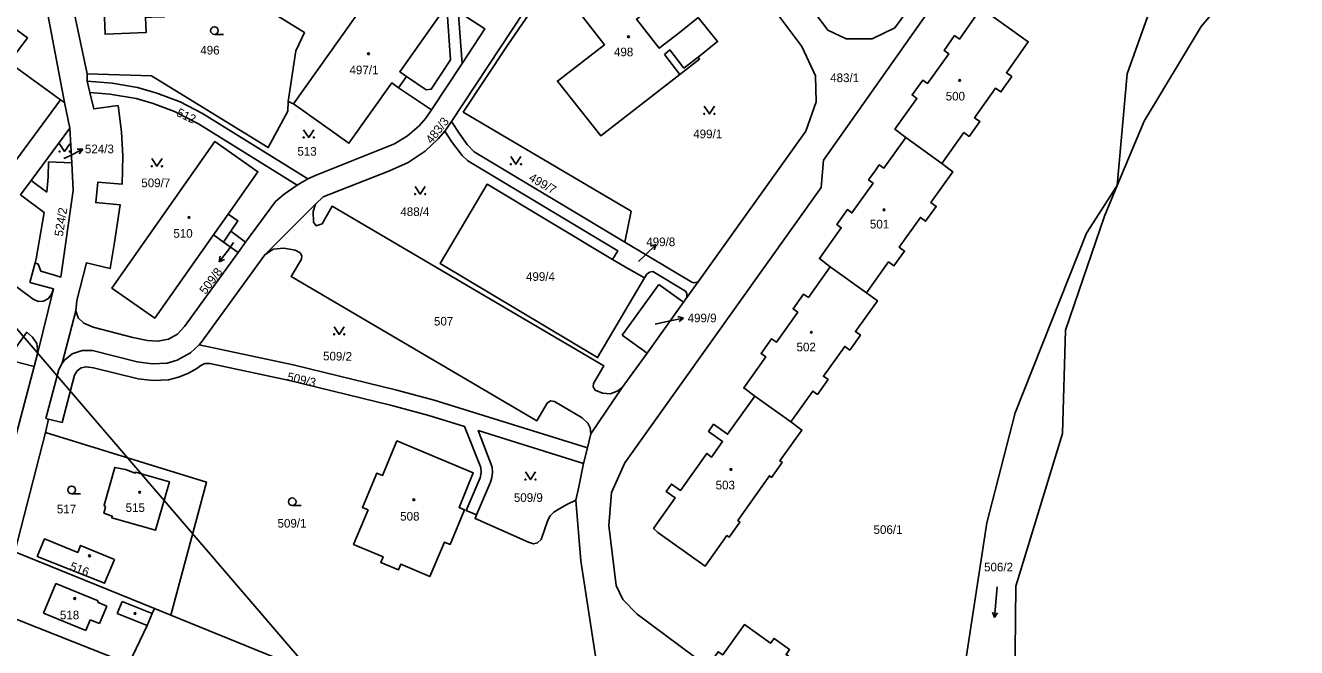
# Model space of a CAD drawing. Extents: x -558358 to -557517, y -1073785 to -1073189.
# Drawn here: x -558075.9 to -557826.1, y -1073555.9 to -1073433.6 of the extents above; entities that cross this region are included whole.
import ezdxf

# ---------------------------------------------------------------- set-up
doc = ezdxf.new("R2010")
doc.units = 0
for name, color, linetype in [('Hranice parcel', 7, 'Continuous'), ('Parcelní čísla', 7, 'Continuous'), ('Pop  PČ popisy', 7, 'Continuous'), ('Vnitřní kresba', 7, 'Continuous'), ('Vrstva 28', 7, 'Continuous'), ('Značky budov', 7, 'Continuous'), ('Značky kultur', 7, 'Continuous')]:
    doc.layers.add(name, color=color, linetype=linetype)

msp = doc.modelspace()

# ---------------------------------------------------------------- linework, layer by layer
at = {"layer": 'Hranice parcel'}
for p, q in [((-558068.26, -1073448.76), (-558079.07, -1073390.9)), ((-558069.9, -1073413.89), (-558063.79, -1073443.12)), ((-558079.09, -1073440.91), (-558069.01, -1073448.19)), ((-557996.12, -1073450.19), (-557990.11, -1073441.11)), ((-558063.79, -1073443.12), (-558063.8, -1073444.57)), ((-558001.05, -1073443.62), (-558002.62, -1073445.83)), ((-558001.05, -1073443.62), (-557997.16, -1073446.28)), ((-558063.8, -1073444.57), (-558063.26, -1073446.76)), ((-557996.12, -1073450.19), (-558002.62, -1073445.83)), ((-558069.01, -1073448.19), (-558068.26, -1073448.76)), ((-558067.19, -1073453.76), (-558068.26, -1073448.76)), ((-558023.22, -1073448.98), (-558024.27, -1073448.53)), ((-558074.8, -1073464.07), (-558067.19, -1073453.76)), ((-558067.19, -1073453.76), (-558066.82, -1073460.61)), ((-557993.5, -1073454.4), (-557992.19, -1073452.45)), ((-557902.93, -1073455.63), (-557895.8, -1073460.74)), ((-557987.76, -1073458.45), (-557958.11, -1073476.19)), ((-558071.37, -1073460.39), (-558066.82, -1073460.61)), ((-558022.54, -1073464.96), (-558020.42, -1073463.73)), ((-558076.9, -1073466.92), (-558074.8, -1073464.07)), ((-558074.8, -1073464.07), (-558071.72, -1073466.37)), ((-558076.9, -1073466.92), (-558072.2, -1073470.34)), ((-558018.89, -1073468.72), (-558028.88, -1073478.68)), ((-558072.2, -1073470.34), (-558073.77, -1073479.5)), ((-558037.01, -1073476.18), (-558035.54, -1073474.05)), ((-558037.01, -1073476.18), (-558034.12, -1073478.2)), ((-558032.65, -1073476.17), (-558035.54, -1073474.05)), ((-558032.65, -1073476.17), (-558034.12, -1073478.2)), ((-557958.11, -1073476.19), (-557944.96, -1073484.06)), ((-558073.98, -1073480.28), (-558075.03, -1073484.15)), ((-558073.77, -1073479.5), (-558073.98, -1073480.28)), ((-557917.76, -1073481.02), (-557910.62, -1073486.13)), ((-558075.03, -1073484.15), (-558070.38, -1073485.35)), ((-558070.38, -1073485.35), (-558073.57, -1073498.15)), ((-557958.62, -1073494.5), (-557951.44, -1073484.51)), ((-557951.44, -1073484.51), (-557946.6, -1073487.99)), ((-557943.74, -1073483.99), (-557945.94, -1073487.07)), ((-557944.96, -1073484.06), (-557944.51, -1073484.17)), ((-557944.51, -1073484.17), (-557943.74, -1073483.99)), ((-557946.6, -1073487.99), (-557953.75, -1073497.99)), ((-557945.94, -1073487.07), (-557946.6, -1073487.99)), ((-557945.94, -1073487.07), (-557945.95, -1073486.25)), ((-558068.7, -1073499.98), (-558066, -1073489.71)), ((-557953.75, -1073497.99), (-557958.62, -1073494.5)), ((-558074.22, -1073500.6), (-558073.57, -1073498.15)), ((-557953.75, -1073497.99), (-557958.67, -1073504.77)), ((-558074.22, -1073500.6), (-558078.34, -1073516.28)), ((-558078.27, -1073499.57), (-558074.22, -1073500.6)), ((-557964.79, -1073513.87), (-557958.67, -1073504.77)), ((-557932.61, -1073506.45), (-557925.51, -1073511.53)), ((-558071.35, -1073510.96), (-558072, -1073513.63)), ((-558071.35, -1073510.96), (-558071.87, -1073510.83)), ((-558068.72, -1073511.63), (-558071.35, -1073510.96)), ((-558072, -1073513.63), (-558078.01, -1073537.04)), ((-557965.43, -1073516.64), (-557964.79, -1073513.87)), ((-557872.13, -1073513.82), (-557881.3, -1073543.83)), ((-557965.43, -1073516.64), (-557966.22, -1073519.7)), ((-557966.22, -1073519.7), (-557967.17, -1073524.31)), ((-557967.17, -1073524.31), (-557967.76, -1073526.9)), ((-557967.76, -1073526.9), (-557969.49, -1073527.78)), ((-558078.01, -1073537.04), (-558050.57, -1073548.21)), ((-558050.57, -1073548.21), (-558047.33, -1073549.53)), ((-558080.96, -1073549.01), (-558055.56, -1073559.09))]:
    msp.add_line(p, q, dxfattribs=at)
for points in [[(-558022.09, -1073311.21), (-558020.08, -1073313.87), (-558000.41, -1073328.2), (-557993.92, -1073334.5), (-557986.04, -1073343.93), (-557967.1, -1073369.2), (-557918.24, -1073434.51), (-557914.64, -1073436.24), (-557909.55, -1073436.22), (-557905.05, -1073434.1), (-557902.57, -1073430.65), (-557891.22, -1073414.37), (-557877.97, -1073395.43)], [(-557997.16, -1073446.28), (-557996.18, -1073446.14), (-557992.37, -1073440.37), (-557993.13, -1073429.99), (-557993.58, -1073428.02), (-558004.25, -1073395), (-558005.55, -1073391.58), (-558006.57, -1073389.94), (-558009.69, -1073386.81), (-558015.69, -1073381.13), (-558022.86, -1073375.1), (-558038.38, -1073364.54), (-558051.46, -1073355.75)], [(-557861.36, -1073465.07), (-557859.38, -1073443.12), (-557853.44, -1073426.35), (-557845.8, -1073410.81), (-557826.12, -1073387.26)], [(-557990.11, -1073441.11), (-557990.95, -1073429.72), (-557991.6, -1073426.99), (-558000.34, -1073399.97), (-557986.42, -1073409.86), (-557979.13, -1073399.38), (-557977.23, -1073400.7), (-557975.75, -1073398.59), (-557966.19, -1073404.96)], [(-557943.74, -1073483.99), (-557922.57, -1073454.37), (-557920.54, -1073448.62), (-557920.67, -1073443.5), (-557923.32, -1073437.76), (-557933.57, -1073424.07), (-557935, -1073422.19), (-557950.81, -1073400.97)], [(-557966.19, -1073404.96), (-557967.15, -1073406.3), (-557970.9, -1073403.86), (-557989.34, -1073431.82), (-557985.62, -1073434.28), (-557990.11, -1073441.11)], [(-557960.73, -1073418.81), (-557955.07, -1073414.41), (-557951.22, -1073411.42), (-557950.93, -1073411.8), (-557947.21, -1073416.59), (-557951.08, -1073419.63), (-557946.63, -1073425.3), (-557955.8, -1073432.39), (-557951.37, -1073438.08), (-557947.44, -1073435.04), (-557943.73, -1073432.04), (-557939.89, -1073436.78), (-557943.7, -1073439.86), (-557943.42, -1073440.21), (-557947.29, -1073443.23), (-557962.81, -1073455.3), (-557971.36, -1073444.52), (-557962.13, -1073437.38), (-557970.6, -1073426.47), (-557970.03, -1073426.04)], [(-557875.08, -1073418.52), (-557880.11, -1073415), (-557884.66, -1073414.11), (-557888.78, -1073417.07), (-557919.08, -1073460.09), (-557919.51, -1073465.45), (-557958.15, -1073519.56), (-557960.76, -1073525.37), (-557961.25, -1073531.9), (-557959.85, -1073543.64), (-557958.52, -1073546.41), (-557955.67, -1073549.33), (-557941.9, -1073559.58)], [(-558079.09, -1073440.91), (-558075.49, -1073436.06), (-558080.13, -1073432.64), (-558078.53, -1073430.7), (-558082.12, -1073428.01), (-558083.47, -1073429.99), (-558090.26, -1073424.91), (-558087.3, -1073420.92), (-558091.08, -1073418.03), (-558093.98, -1073421.97), (-558100.23, -1073417.28)], [(-557968.81, -1073419.39), (-557969.8, -1073419.14), (-557970.66, -1073419.77), (-557992.19, -1073452.45)], [(-557834.15, -1073421.11), (-557844.86, -1073433.81), (-557856.07, -1073452.41), (-557861.36, -1073465.07)], [(-558049.8, -1073431.93), (-558048.54, -1073431.88), (-558048.64, -1073429.15), (-558049.91, -1073429.2), (-558050.08, -1073422.86), (-558052.56, -1073422.66), (-558052.57, -1073422.02), (-558060.76, -1073422.24), (-558060.26, -1073435.32), (-558052.21, -1073435.02), (-558052.32, -1073432.02), (-558049.8, -1073431.93)], [(-558023.22, -1073448.98), (-558004.82, -1073423.06), (-557993.94, -1073430.83), (-558002.36, -1073442.69), (-558001.05, -1073443.62)], [(-557971.99, -1073423.64), (-557977.49, -1073432.15), (-557981.25, -1073437.64), (-557989.89, -1073450.63)], [(-558024.27, -1073448.53), (-558022.77, -1073438.58), (-558021.1, -1073435.02), (-558027.22, -1073431.17)], [(-557902.93, -1073455.63), (-557905.05, -1073454), (-557900.72, -1073447.94), (-557901.66, -1073447.27), (-557899.55, -1073444.33), (-557898.62, -1073444.99), (-557894.46, -1073439.18), (-557895.4, -1073438.51), (-557893.33, -1073435.61), (-557892.39, -1073436.28), (-557888.07, -1073430.23), (-557878.84, -1073436.82), (-557883.15, -1073442.9), (-557882.08, -1073443.65), (-557884.22, -1073446.66), (-557885.28, -1073445.91), (-557889.41, -1073451.73), (-557888.35, -1073452.48), (-557890.43, -1073455.41), (-557891.49, -1073454.66), (-557895.8, -1073460.74)], [(-558063.79, -1073443.12), (-558051.12, -1073443.51), (-558028.21, -1073457.62), (-558024.35, -1073450.45), (-558024.27, -1073448.53)], [(-558020.42, -1073463.73), (-558041.1, -1073450.88), (-558045.53, -1073448.61), (-558050.06, -1073446.9), (-558053.87, -1073445.77), (-558058.84, -1073444.97), (-558063.8, -1073444.57)], [(-558002.62, -1073445.83), (-558003.93, -1073444.91), (-558012.33, -1073456.75), (-558023.22, -1073448.98)], [(-558069.01, -1073448.19), (-558089.39, -1073475.8), (-558089.17, -1073475.95), (-558090.09, -1073477.27), (-558100.29, -1073469.58), (-558095.61, -1073463.24)], [(-558066, -1073489.71), (-558065.83, -1073487.66), (-558063.93, -1073480.27), (-558059.28, -1073481.39), (-558058.41, -1073476.28), (-558057.32, -1073468.85), (-558062.09, -1073468.41), (-558061.69, -1073464.41), (-558056.9, -1073464.79), (-558056.8, -1073459.32), (-558057.06, -1073454.51), (-558057.72, -1073449.34), (-558062.47, -1073450), (-558063.26, -1073446.76)], [(-558063.26, -1073446.76), (-558059.34, -1073447.1), (-558054.18, -1073447.94), (-558050.82, -1073448.92), (-558046.65, -1073450.5), (-558041.92, -1073452.93), (-558022.54, -1073464.96)], [(-558020.42, -1073463.73), (-558018.76, -1073463.03), (-558003.4, -1073456.89), (-558000.84, -1073455.32), (-557998.53, -1073453.34), (-557997.26, -1073451.83), (-557996.12, -1073450.19)], [(-557989.89, -1073450.63), (-557956.91, -1073470.13), (-557958.11, -1073476.19)], [(-557992.19, -1073452.45), (-557990.57, -1073454.98), (-557989.11, -1073456.98), (-557987.76, -1073458.45)], [(-558018.89, -1073468.72), (-558017.43, -1073467.28), (-558004.36, -1073462.2), (-558000.71, -1073460.54), (-557997.38, -1073458.33), (-557994.81, -1073455.9), (-557993.5, -1073454.4)], [(-557960.53, -1073479.61), (-557959.52, -1073477.88), (-557988.99, -1073460.22), (-557990.09, -1073459.14), (-557992.19, -1073456.42), (-557993.5, -1073454.4)], [(-557917.76, -1073481.02), (-557919.89, -1073479.42), (-557915.58, -1073473.37), (-557916.49, -1073472.72), (-557914.4, -1073469.79), (-557913.49, -1073470.44), (-557909.33, -1073464.6), (-557910.24, -1073463.95), (-557908.96, -1073462.17), (-557908.15, -1073461.02), (-557907.24, -1073461.67), (-557902.93, -1073455.63)], [(-558035.54, -1073474.05), (-558034.14, -1073472.03), (-558036.08, -1073470.66), (-558030.24, -1073462.37), (-558038.66, -1073456.4), (-558058.9, -1073485.25), (-558050.49, -1073491.12), (-558038.98, -1073474.78), (-558037.01, -1073476.18)], [(-558066.82, -1073460.61), (-558066.53, -1073466.05), (-558068.98, -1073483.05), (-558070.17, -1073482.68), (-558072.89, -1073481.86), (-558073.42, -1073480.5), (-558073.98, -1073480.28)], [(-558071.72, -1073466.37), (-558071.45, -1073463.36), (-558071.37, -1073460.39)], [(-557895.8, -1073460.74), (-557893.65, -1073462.39), (-557897.97, -1073468.43), (-557896.94, -1073469.17), (-557899.02, -1073472.08), (-557900.05, -1073471.34), (-557904.22, -1073477.17), (-557903.16, -1073477.93), (-557905.25, -1073480.84), (-557906.3, -1073480.09), (-557910.62, -1073486.13)], [(-558022.54, -1073464.96), (-558025.08, -1073466.74), (-558026.8, -1073468.19), (-558032.65, -1073476.17)], [(-557954.23, -1073483.22), (-557963.48, -1073498.87), (-557994.38, -1073480.4), (-557985.2, -1073464.81), (-557960.53, -1073479.61)], [(-557897.48, -1073592.57), (-557892.38, -1073566.43), (-557887.02, -1073531.37), (-557881.44, -1073509.74), (-557867.37, -1073474.4), (-557861.36, -1073465.07)], [(-557861.36, -1073465.07), (-557863.88, -1073471.1), (-557871.54, -1073493.51), (-557872.13, -1073513.82)], [(-557958.67, -1073504.77), (-557959.52, -1073505.42), (-557960.94, -1073505.97), (-557962.48, -1073505.9), (-557963.93, -1073505.3), (-557964.34, -1073504.64), (-557964.29, -1073503.98), (-557962.25, -1073500.52), (-558015.64, -1073469.14), (-558017.62, -1073472.56), (-558018.8, -1073472.98), (-558019.32, -1073472.29), (-558019.38, -1073470.18), (-558018.89, -1073468.72)], [(-558073.57, -1073498.15), (-558073.51, -1073497.13), (-558073.7, -1073496.11), (-558074.52, -1073494.85), (-558075.64, -1073493.89), (-558078.28, -1073497.56), (-558092.71, -1073486.96), (-558086.45, -1073478.46)], [(-558070.38, -1073485.35), (-558070.76, -1073486.43), (-558071.41, -1073487.24), (-558072.33, -1073487.8), (-558073.38, -1073487.88), (-558074.36, -1073487.41), (-558086.45, -1073478.46)], [(-558034.12, -1073478.2), (-558044.67, -1073492.79), (-558046.03, -1073494.25), (-558047.82, -1073495.28), (-558049.88, -1073495.66), (-558051.92, -1073495.51), (-558054.81, -1073494.91), (-558062.59, -1073492.91), (-558064.44, -1073492.11), (-558065.56, -1073491.04), (-558066, -1073489.71)], [(-558028.88, -1073478.68), (-558041.38, -1073495.88), (-558041.79, -1073496.35)], [(-558028.88, -1073478.68), (-558027.22, -1073477.58), (-558025.14, -1073477.37), (-558022.91, -1073477.77), (-558021.94, -1073478.27), (-558021.58, -1073478.9), (-558021.69, -1073479.54), (-558023.7, -1073482.95), (-557975.42, -1073511.29), (-557973.41, -1073507.84), (-557972.71, -1073507.36), (-557971.95, -1073507.53), (-557966.49, -1073510.72), (-557965.39, -1073511.77), (-557964.96, -1073512.7), (-557964.79, -1073513.87)], [(-557954.23, -1073483.22), (-557957.38, -1073481.46), (-557960.53, -1073479.61)], [(-557932.61, -1073506.45), (-557934.75, -1073504.84), (-557930.41, -1073498.76), (-557931.35, -1073498.09), (-557930.07, -1073496.31), (-557929.28, -1073495.19), (-557928.34, -1073495.86), (-557924.14, -1073489.96), (-557925.07, -1073489.3), (-557922.99, -1073486.39), (-557922.06, -1073487.05), (-557917.76, -1073481.02)], [(-557945.95, -1073486.25), (-557946.2, -1073485.81), (-557952.65, -1073481.96), (-557953.3, -1073482.07), (-557953.78, -1073482.47), (-557954.23, -1073483.22)], [(-557910.62, -1073486.13), (-557908.48, -1073487.72), (-557912.81, -1073493.77), (-557911.82, -1073494.47), (-557913.92, -1073497.39), (-557914.9, -1073496.69), (-557919.09, -1073502.55), (-557918.19, -1073503.19), (-557920.29, -1073506.11), (-557921.18, -1073505.47), (-557925.51, -1073511.53)], [(-558068.7, -1073499.98), (-558068.26, -1073499.37), (-558066.7, -1073498.15), (-558064.79, -1073497.48), (-558062.72, -1073497.49), (-558053.98, -1073499.73), (-558051.03, -1073500.12), (-558048.06, -1073499.96), (-558046.1, -1073499.41), (-558043.49, -1073497.93), (-558041.79, -1073496.35)], [(-558041.79, -1073496.35), (-558023.3, -1073500.28), (-558002.91, -1073505.27), (-557995.6, -1073507.26), (-557965.43, -1073516.64)], [(-558071.87, -1073510.83), (-558069.32, -1073501.19), (-558068.7, -1073499.98)], [(-557987.27, -1073529.77), (-557989.29, -1073528.94), (-557986.56, -1073522.48), (-557986.36, -1073521.52), (-557986.44, -1073520.51), (-557989.6, -1073512.4), (-557996.64, -1073510.25), (-558004.14, -1073508.22), (-558024.01, -1073503.35), (-558039.66, -1073500.03), (-558040.64, -1073500.03), (-558041.42, -1073500.4), (-558042.23, -1073501), (-558043.97, -1073502.01), (-558045.84, -1073502.74), (-558047.8, -1073503.22), (-558050.8, -1073503.37), (-558053.79, -1073503.03), (-558062.52, -1073500.9), (-558063.99, -1073500.68), (-558064.96, -1073500.91), (-558065.77, -1073501.48), (-558066.28, -1073502.33), (-558068.72, -1073511.63)], [(-557932.61, -1073506.45), (-557937.92, -1073513.94), (-557940.69, -1073511.97), (-557941.71, -1073513.4), (-557938.93, -1073515.37), (-557941.12, -1073518.46), (-557942.01, -1073517.7), (-557947.21, -1073524.97), (-557948.97, -1073523.73), (-557949.99, -1073525.17), (-557948.24, -1073526.41), (-557952.49, -1073532.47), (-557951.63, -1073533.27), (-557942.33, -1073539.86), (-557938.05, -1073533.83), (-557937.62, -1073534.14), (-557935.52, -1073531.19), (-557935.95, -1073530.88), (-557929.72, -1073522.11), (-557929.27, -1073522.43), (-557927.19, -1073519.5), (-557927.64, -1073519.19), (-557923.33, -1073513.13), (-557925.51, -1073511.53)], [(-558047.33, -1073549.53), (-558040.31, -1073523.33), (-558072, -1073513.63)], [(-557987.27, -1073529.77), (-557984.55, -1073523.36), (-557984.23, -1073522.42), (-557984.14, -1073521.45), (-557984.2, -1073520.39), (-557986.94, -1073513.23), (-557966.22, -1073519.7)], [(-558008.57, -1073528.8), (-558011.42, -1073535.59), (-558005.63, -1073538.02), (-558006.1, -1073539.13), (-558002.62, -1073540.59), (-558002.16, -1073539.49), (-557996.41, -1073541.91), (-557993.56, -1073535.14), (-557992.45, -1073535.6), (-557989.61, -1073528.81), (-557990.71, -1073528.34), (-557987.91, -1073521.54), (-558002.9, -1073515.24), (-558005.74, -1073522.02), (-558006.84, -1073521.56), (-558009.68, -1073528.33), (-558008.57, -1073528.8)], [(-558060.16, -1073528.26), (-558060.48, -1073529.48), (-558058.86, -1073530.06), (-558058.94, -1073530.35), (-558050.37, -1073532.81), (-558047.63, -1073523.32), (-558054.29, -1073521.4), (-558054.34, -1073521.59), (-558056.23, -1073520.85), (-558058.32, -1073520.45), (-558060.47, -1073527.85), (-558060.16, -1073528.26)], [(-557969.49, -1073527.78), (-557971.24, -1073528.71), (-557972.09, -1073529.24), (-557972.78, -1073529.97), (-557973.26, -1073530.86), (-557974.57, -1073534.63), (-557975.26, -1073535.31), (-557976.1, -1073535.45), (-557977.05, -1073535.17), (-557987.55, -1073530.47), (-557987.27, -1073529.77)], [(-557961.12, -1073576.24), (-557962.13, -1073568.62), (-557962.94, -1073563.5), (-557966.76, -1073538.79), (-557967.76, -1073526.9)], [(-558058.43, -1073538.53), (-558065.06, -1073535.79), (-558065.61, -1073537.16), (-558072.15, -1073534.51), (-558073.59, -1073537.94), (-558060.37, -1073543.23), (-558058.43, -1073538.53)], [(-557881.3, -1073543.83), (-557881.54, -1073569.39), (-557886.18, -1073582.51)], [(-558055.56, -1073559.09), (-558052.02, -1073551.52), (-558051, -1073549.15), (-558050.57, -1073548.21)], [(-557977.41, -1073591.02), (-557981.5, -1073577.12), (-557984.25, -1073575.17), (-558047.33, -1073549.53)], [(-557944.07, -1073562.64), (-557943.15, -1073563.3), (-557947.42, -1073569.28), (-557934.16, -1073578.7), (-557929.93, -1073572.77), (-557928.96, -1073573.46), (-557924.72, -1073567.52), (-557925.63, -1073566.74), (-557921.33, -1073560.9), (-557926.44, -1073557.23), (-557925.76, -1073556.27), (-557928.81, -1073554.08), (-557929.5, -1073555.03), (-557934.61, -1073551.36), (-557938.85, -1073557.29), (-557939.81, -1073556.68), (-557941.9, -1073559.58)]]:
    msp.add_lwpolyline(points, dxfattribs=at)
at = {"layer": 'Pop  PČ popisy'}
for p, q in [((-558067.34, -1073459.26), (-558064.64, -1073457.94)), ((-558064.64, -1073457.94), (-558065.76, -1073457.93)), ((-558064.64, -1073457.94), (-558065.32, -1073458.83)), ((-558068.37, -1073459.77), (-558067.34, -1073459.26)), ((-558036.02, -1073477.67), (-558037.83, -1073480.07)), ((-558035, -1073476.29), (-558036.02, -1073477.67)), ((-557954.15, -1073478.76), (-557951.99, -1073476.68)), ((-557951.99, -1073476.68), (-557953.06, -1073477.01)), ((-557951.99, -1073476.68), (-557952.36, -1073477.73)), ((-558037.83, -1073480.07), (-558037.62, -1073478.97)), ((-558037.83, -1073480.07), (-558036.82, -1073479.57)), ((-557955.41, -1073479.99), (-557954.15, -1073478.76)), ((-557949.53, -1073491.73), (-557946.59, -1073491.11)), ((-557946.59, -1073491.11), (-557947.68, -1073490.82)), ((-557946.59, -1073491.11), (-557947.47, -1073491.8)), ((-557952.15, -1073492.28), (-557949.53, -1073491.73))]:
    msp.add_line(p, q, dxfattribs=at)
at = {"layer": 'Vnitřní kresba'}
for p, q in [((-557950.33, -1073439.32), (-557949.26, -1073438.42)), ((-557949.26, -1073438.42), (-557946.5, -1073442)), ((-557950.33, -1073439.32), (-557947.29, -1073443.23)), ((-557946.5, -1073442), (-557943.7, -1073439.86)), ((-558038.98, -1073474.78), (-558036.08, -1073470.66)), ((-558072.33, -1073549.11), (-558069.95, -1073543.28)), ((-558069.95, -1073543.28), (-558061.62, -1073546.69)), ((-558061.73, -1073546.96), (-558061.62, -1073546.69)), ((-558061.73, -1073546.96), (-558059.91, -1073547.71)), ((-558061.37, -1073551.16), (-558059.91, -1073547.71)), ((-558057.87, -1073549.14), (-558056.91, -1073546.78)), ((-558056.91, -1073546.78), (-558051, -1073549.15)), ((-558072.33, -1073549.11), (-558064.04, -1073552.48)), ((-558064.04, -1073552.48), (-558063.17, -1073550.4)), ((-558063.17, -1073550.4), (-558061.37, -1073551.16)), ((-558057.87, -1073549.14), (-558052.02, -1073551.52))]:
    msp.add_line(p, q, dxfattribs=at)
at = {"layer": 'Vrstva 28'}
msp.add_line((-558150.5, -1073408.33), (-557941.76, -1073651.48), dxfattribs=at)
at = {"layer": 'Značky budov'}
for centre in [(-557957.4, -1073435.82), (-558008.5, -1073439.16), (-557892.32, -1073444.4), (-558043.77, -1073471.33), (-557907.2, -1073469.84), (-557921.47, -1073493.92), (-557937.27, -1073520.85), (-558053.47, -1073525.34), (-557999.58, -1073526.81), (-558063.31, -1073537.83), (-558066.22, -1073546.23), (-558054.38, -1073549.16)]:
    msp.add_circle(centre, 0.175, dxfattribs=at)
at = {"layer": 'Značky kultur'}
for p, q in [((-558038.77, -1073435.36), (-558037.02, -1073435.36)), ((-558066.82, -1073525.63), (-558065.07, -1073525.63)), ((-558023.49, -1073527.96), (-558021.74, -1073527.96)), ((-557884.95, -1073543.96), (-557885.47, -1073549.94)), ((-557885.47, -1073549.94), (-557885.89, -1073548.92)), ((-557885.47, -1073549.94), (-557884.89, -1073549.01))]:
    msp.add_line(p, q, dxfattribs=at)
for points in [[(-557942.51, -1073449.49), (-557941.51, -1073450.99), (-557940.51, -1073449.49)], [(-558021.24, -1073454.11), (-558020.24, -1073455.61), (-558019.24, -1073454.11)], [(-558069.21, -1073456.87), (-558068.21, -1073458.37), (-558067.21, -1073456.87)], [(-558051.07, -1073459.77), (-558050.07, -1073461.27), (-558049.07, -1073459.77)], [(-557980.53, -1073459.39), (-557979.53, -1073460.89), (-557978.53, -1073459.39)], [(-557999.34, -1073465.25), (-557998.34, -1073466.75), (-557997.34, -1073465.25)], [(-558015.26, -1073492.81), (-558014.26, -1073494.31), (-558013.26, -1073492.81)], [(-557977.66, -1073521.36), (-557976.66, -1073522.86), (-557975.66, -1073521.36)]]:
    msp.add_lwpolyline(points, dxfattribs=at)
for centre, radius in [((-558038.77, -1073434.61), 0.75), ((-557942.51, -1073450.99), 0.1), ((-557940.51, -1073450.99), 0.1), ((-558021.24, -1073455.61), 0.1), ((-558019.24, -1073455.61), 0.1), ((-558069.21, -1073458.37), 0.1), ((-558067.21, -1073458.37), 0.1), ((-558051.07, -1073461.27), 0.1), ((-558049.07, -1073461.27), 0.1), ((-557980.53, -1073460.89), 0.1), ((-557978.53, -1073460.89), 0.1), ((-557999.34, -1073466.75), 0.1), ((-557997.34, -1073466.75), 0.1), ((-558015.26, -1073494.31), 0.1), ((-558013.26, -1073494.31), 0.1), ((-557977.66, -1073522.86), 0.1), ((-557975.66, -1073522.86), 0.1), ((-558066.82, -1073524.88), 0.75), ((-558023.49, -1073527.21), 0.75)]:
    msp.add_circle(centre, radius, dxfattribs=at)

# ---------------------------------------------------------------- texts
at = {"layer": 'Parcelní čísla'}
for s, p in [('496', (-558041.55, -1073439.31)), ('498', (-557960.26, -1073439.66)), ('497/1', (-558012.23, -1073443.2)), ('483/1', (-557917.77, -1073444.74)), ('500', (-557895.07, -1073448.35)), ('499/1', (-557944.68, -1073455.77)), ('524/3', (-558064.22, -1073458.72)), ('513', (-558022.47, -1073459.2)), ('509/7', (-558053.14, -1073465.39)), ('488/4', (-558002.23, -1073471.06)), ('510', (-558046.84, -1073475.32)), ('501', (-557909.97, -1073473.5)), ('499/8', (-557953.91, -1073476.98)), ('499/4', (-557977.55, -1073483.8)), ('507', (-557995.63, -1073492.58)), ('499/9', (-557945.79, -1073491.94)), ('502', (-557924.38, -1073497.65)), ('503', (-557940.28, -1073524.78)), ('509/9', (-557979.93, -1073527.24)), ('517', (-558069.74, -1073529.5)), ('515', (-558056.22, -1073529.21)), ('509/1', (-558026.37, -1073532.29)), ('508', (-558002.27, -1073530.91)), ('506/1', (-557909.25, -1073533.53)), ('506/2', (-557887.53, -1073540.89)), ('518', (-558069.13, -1073550.31))]:
    msp.add_text(s, height=1.7, dxfattribs=at).set_placement(p)
for s, rotation, p in [('512', 335, (-558046.36, -1073451.33)), ('483/3', 52, (-557996.07, -1073456.97)), ('499/7', 330, (-557977.15, -1073463.99)), ('524/2', 81, (-558068.56, -1073475.16)), ('509/8', 53, (-558040.52, -1073486.58)), ('509/2', 359, (-558017.44, -1073499.41)), ('509/3', 347, (-558024.6, -1073503.39)), ('516', 339, (-558067.34, -1073540.57))]:
    msp.add_text(s, height=1.7, rotation=rotation, dxfattribs=at).set_placement(p)

doc.saveas('drawing.dxf')
